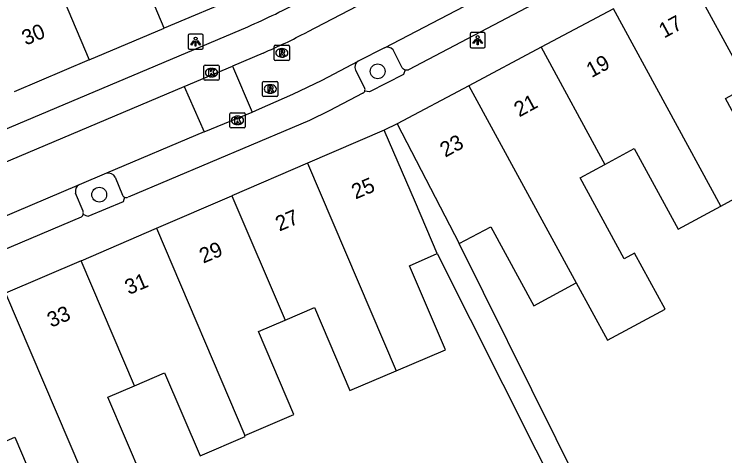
# Model space of a CAD drawing. Extents: x 159718 to 160783, y 383290 to 384030.
# Drawn here: x 160428.04 to 160474.83, y 383447.83 to 383476.93 of the extents above; entities that cross this region are included whole.
import ezdxf

# ---------------------------------------------------------------- set-up
doc = ezdxf.new("R2010")
doc.units = 0
for name, color, linetype in [('IMGEO_Boom', 7, 'Continuous'), ('IMGEO_Kolk', 7, 'Continuous'), ('IMGEO_Lichtpunt', 7, 'Continuous'), ('IMGEO_Pand', 7, 'Continuous'), ('IMGEO_Pand_nummerreeks', 7, 'Continuous'), ('IMGEO_Parkeervlak_open', 7, 'Continuous'), ('IMGEO_Rijbaan_lokaal_open', 7, 'Continuous'), ('IMGEO_Rioolput', 7, 'Continuous'), ('IMGEO_Voetpad_open', 7, 'Continuous')]:
    doc.layers.add(name, color=color, linetype=linetype)

msp = doc.modelspace()

# ---------------------------------------------------------------- linework, layer by layer
at = {"layer": 'IMGEO_Boom'}
for centre in [(160451.975, 383473.159), (160433.635, 383465.037)]:
    msp.add_circle(centre, 0.489, dxfattribs=at)
at = {"layer": 'IMGEO_Kolk'}
for p, q in [((160440.529, 383472.649), (160440.529, 383473.501)), ((160440.604, 383473.575), (160441.456, 383473.575)), ((160441.53, 383473.501), (160441.53, 383472.649)), ((160441.017, 383473.355), (160441.042, 383473.355)), ((160441.456, 383472.575), (160440.604, 383472.575)), ((160441.04, 383472.795), (160441.015, 383472.795)), ((160442.242, 383469.503), (160442.242, 383470.355)), ((160442.317, 383470.429), (160443.169, 383470.429)), ((160443.243, 383470.355), (160443.243, 383469.503)), ((160442.73, 383470.209), (160442.755, 383470.209)), ((160443.169, 383469.429), (160442.317, 383469.429)), ((160442.753, 383469.649), (160442.728, 383469.649))]:
    msp.add_line(p, q, dxfattribs=at)
for points in [[(160440.529, 383472.649), (160440.529, 383473.501)], [(160440.604, 383473.575), (160441.456, 383473.575)], [(160441.53, 383473.501), (160441.53, 383472.649)], [(160440.85, 383473.275), (160440.973, 383473.275), (160440.973, 383473.124), (160441.103, 383473.275), (160441.267, 383473.275), (160441.121, 383473.124), (160441.274, 383472.875), (160441.122, 383472.875), (160441.037, 383473.039), (160440.973, 383472.972), (160440.973, 383472.875), (160440.85, 383472.875), (160440.85, 383473.275)], [(160441.456, 383472.575), (160440.604, 383472.575)], [(160442.242, 383469.503), (160442.242, 383470.355)], [(160442.317, 383470.429), (160443.169, 383470.429)], [(160443.243, 383470.355), (160443.243, 383469.503)], [(160442.563, 383470.129), (160442.686, 383470.129), (160442.686, 383469.978), (160442.816, 383470.129), (160442.98, 383470.129), (160442.834, 383469.978), (160442.987, 383469.729), (160442.835, 383469.729), (160442.75, 383469.893), (160442.686, 383469.826), (160442.686, 383469.729), (160442.563, 383469.729), (160442.563, 383470.129)], [(160443.169, 383469.429), (160442.317, 383469.429)]]:
    msp.add_lwpolyline(points, dxfattribs=at)
for centre, start, end in [((160440.606, 383473.499), 91.552, 178.448), ((160440.606, 383473.499), 91.552, 178.448), ((160441.454, 383473.499), 1.552, 88.448), ((160441.454, 383473.499), 1.552, 88.448), ((160440.606, 383472.651), 181.552, 268.448), ((160440.606, 383472.651), 181.552, 268.448), ((160441.454, 383472.651), 271.552, 358.448), ((160441.454, 383472.651), 271.552, 358.448), ((160442.319, 383470.353), 91.552, 178.448), ((160442.319, 383470.353), 91.552, 178.448), ((160443.167, 383470.353), 1.552, 88.448), ((160443.167, 383470.353), 1.552, 88.448), ((160442.319, 383469.505), 181.552, 268.448), ((160442.319, 383469.505), 181.552, 268.448), ((160443.167, 383469.505), 271.552, 358.448), ((160443.167, 383469.505), 271.552, 358.448)]:
    msp.add_arc(centre, 0.0765, start, end, dxfattribs=at)
for centre, major_axis, ratio, start_param, end_param in [((160441.016, 383473.075), (-0.387, 0.002), 0.722429, 4.712389, 7.853982), ((160441.041, 383473.075), (-0.39, 0.002), 0.717154, 1.570796, 4.712389), ((160442.729, 383469.929), (-0.387, 0.002), 0.722429, 4.712389, 7.853982), ((160442.754, 383469.929), (-0.39, 0.002), 0.717154, 1.570796, 4.712389)]:
    msp.add_ellipse(centre, major_axis=major_axis, ratio=ratio, start_param=start_param, end_param=end_param, dxfattribs=at)
at = {"layer": 'IMGEO_Lichtpunt'}
for p, q in [((160439.483, 383475.522), (160439.483, 383474.715)), ((160439.483, 383475.522), (160439.483, 383474.715)), ((160440.385, 383475.617), (160439.577, 383475.617)), ((160440.385, 383475.617), (160439.577, 383475.617)), ((160440.479, 383474.715), (160440.479, 383475.522)), ((160440.479, 383474.715), (160440.479, 383475.522)), ((160458.058, 383475.615), (160458.058, 383474.808)), ((160458.058, 383475.615), (160458.058, 383474.808)), ((160458.96, 383475.71), (160458.152, 383475.71)), ((160458.96, 383475.71), (160458.152, 383475.71)), ((160459.054, 383474.808), (160459.054, 383475.615)), ((160459.054, 383474.808), (160459.054, 383475.615)), ((160439.577, 383474.621), (160440.385, 383474.621)), ((160439.577, 383474.621), (160440.385, 383474.621)), ((160458.152, 383474.714), (160458.96, 383474.714)), ((160458.152, 383474.714), (160458.96, 383474.714))]:
    msp.add_line(p, q, dxfattribs=at)
for points in [[(160439.857, 383475.186), (160439.896, 383475.158), (160439.708, 383474.896), (160439.67, 383474.923), (160439.857, 383475.186)], [(160439.959, 383475.138), (160440.006, 383475.138), (160440.006, 383474.816), (160439.959, 383474.816), (160439.959, 383475.138)], [(160440.069, 383475.158), (160440.107, 383475.185), (160440.294, 383474.923), (160440.255, 383474.895), (160440.069, 383475.158)], [(160458.432, 383475.279), (160458.471, 383475.251), (160458.283, 383474.989), (160458.245, 383475.016), (160458.432, 383475.279)], [(160458.534, 383475.231), (160458.581, 383475.231), (160458.581, 383474.909), (160458.534, 383474.909), (160458.534, 383475.231)], [(160458.644, 383475.251), (160458.682, 383475.278), (160458.869, 383475.016), (160458.83, 383474.988), (160458.644, 383475.251)]]:
    msp.add_lwpolyline(points, dxfattribs=at)
for centre in [(160439.982, 383475.32), (160458.557, 383475.413)]:
    msp.add_circle(centre, 0.0994, dxfattribs=at)
for centre, start, end in [((160439.577, 383475.522), 90, 180), ((160439.577, 383475.522), 90, 180), ((160440.385, 383475.522), 0, 90), ((160440.385, 383475.522), 0, 90), ((160458.152, 383475.615), 90, 180), ((160458.152, 383475.615), 90, 180), ((160458.96, 383475.615), 0, 90), ((160458.96, 383475.615), 0, 90), ((160439.577, 383474.715), 180, 270), ((160439.577, 383474.715), 180, 270), ((160440.385, 383474.715), 270, 0), ((160440.385, 383474.715), 270, 360), ((160458.152, 383474.808), 180, 270), ((160458.152, 383474.808), 180, 270), ((160458.96, 383474.808), 270, 0), ((160458.96, 383474.808), 270, 360)]:
    msp.add_arc(centre, 0.0946, start, end, dxfattribs=at)
at = {"layer": 'IMGEO_Pand'}
for points in [[(160437.922, 383476.001), (160432.152, 383489.667), (160432.064, 383489.875)], [(160429.617, 383481.871), (160432.979, 383473.909)], [(160476.413, 383472.214), (160472.268, 383479.822)], [(160442.949, 383478.128), (160437.922, 383476.001)], [(160467.502, 383477.285), (160462.733, 383474.747)], [(160474.581, 383464.288), (160467.502, 383477.285)], [(160432.979, 383473.909), (160437.922, 383476.001)], [(160462.733, 383474.747), (160457.967, 383472.21)], [(160462.733, 383474.747), (160466.94, 383467.027)], [(160432.979, 383473.909), (160428.035, 383471.817)], [(160457.967, 383472.21), (160453.253, 383469.701)], [(160457.967, 383472.21), (160465.039, 383459.226)], [(160474.581, 383464.288), (160477.78, 383466.03), (160474.869, 383471.373), (160476.413, 383472.214)], [(160452.408, 383469.29), (160447.343, 383467.106)], [(160455.891, 383461.15), (160454.461, 383464.515), (160452.408, 383469.29)], [(160453.253, 383469.701), (160457.334, 383461.812)], [(160466.94, 383467.027), (160468.871, 383468.079), (160471.77, 383462.757), (160474.581, 383464.288)], [(160447.343, 383467.106), (160442.373, 383464.964)], [(160447.343, 383467.106), (160453.18, 383453.418)], [(160465.039, 383459.226), (160467.103, 383455.437), (160470.895, 383457.501), (160468.888, 383461.187), (160468.209, 383460.817), (160465.309, 383466.139), (160466.94, 383467.027)], [(160437.405, 383462.822), (160442.373, 383464.964)], [(160442.373, 383464.964), (160445.87, 383456.765)], [(160432.435, 383460.679), (160437.405, 383462.822)], [(160437.405, 383462.822), (160443.225, 383449.175)], [(160457.334, 383461.812), (160459.434, 383462.908), (160462.264, 383457.714), (160465.039, 383459.226)], [(160453.18, 383453.418), (160456.443, 383454.809), (160454.078, 383460.356), (160455.891, 383461.15)], [(160432.435, 383460.679), (160427.467, 383458.537)], [(160435.948, 383452.441), (160432.435, 383460.679)], [(160427.467, 383458.537), (160433.298, 383444.865)], [(160445.87, 383456.765), (160447.814, 383457.594), (160450.146, 383452.125), (160453.18, 383453.418)], [(160443.225, 383449.175), (160446.457, 383450.553), (160444.125, 383456.021), (160445.87, 383456.765)], [(160435.948, 383452.441), (160437.943, 383453.292), (160440.272, 383447.829), (160443.256, 383449.102), (160443.225, 383449.175)], [(160433.765, 383445.064), (160436.521, 383446.24), (160434.195, 383451.694), (160435.948, 383452.441)], [(160423.676, 383445.899), (160426.704, 383447.19), (160426.244, 383448.268), (160428.072, 383449.047), (160430.385, 383443.623), (160430.486, 383443.666)]]:
    msp.add_lwpolyline(points, dxfattribs=at)
at = {"layer": 'IMGEO_Parkeervlak_open'}
for points in [[(160453.585, 383473.403), (160452.985, 383474.573)], [(160450.507, 383473.248), (160451.108, 383472.078)], [(160434.69, 383466.181), (160435.166, 383465.011)], [(160432.575, 383463.94), (160432.07, 383465.144)]]:
    msp.add_lwpolyline(points, dxfattribs=at)
for centre, radius, start, end in [((160452.626, 383474.301), 0.45, 37.2033, 116.1323), ((160450.932, 383473.432), 0.464, 122.1039, 203.4256), ((160453.883, 383473.626), 0.372, 216.8563, 255.3756), ((160450.88, 383471.956), 0.259, 339.3881, 28.1329), ((160434.233, 383465.945), 0.515, 27.2902, 102.7529), ((160432.575, 383465.252), 0.516, 121.3704, 192.0307), ((160435.413, 383465.111), 0.266, 201.9501, 245.5948), ((160432.242, 383463.842), 0.347, 341.9589, 16.3642)]:
    msp.add_arc(centre, radius, start, end, dxfattribs=at)
at = {"layer": 'IMGEO_Rijbaan_lokaal_open'}
for points in [[(160473.083, 383489.163), (160447.32, 383475.749)], [(160452.428, 383474.705), (160468.689, 383483.205)], [(160452.428, 383474.705), (160450.686, 383473.825)], [(160444.425, 383474.364), (160442.414, 383473.513)], [(160439.234, 383472.166), (160442.414, 383473.513)], [(160442.414, 383473.513), (160443.698, 383470.478)], [(160443.698, 383470.478), (160444.194, 383470.688), (160446.383, 383471.66), (160448.326, 383472.59), (160450.686, 383473.825)], [(160414.256, 383461.59), (160439.234, 383472.166)], [(160439.234, 383472.166), (160440.546, 383469.169)], [(160440.546, 383469.169), (160443.698, 383470.478)], [(160440.546, 383469.169), (160434.119, 383466.447)], [(160434.119, 383466.447), (160432.306, 383465.692)], [(160432.306, 383465.692), (160420.476, 383460.662)]]:
    msp.add_lwpolyline(points, dxfattribs=at)
msp.add_arc((160427.937, 383512.547), 41.591, 293.3559, 297.778, dxfattribs=at)
at = {"layer": 'IMGEO_Rioolput'}
for p, q in [((160445.16, 383473.95), (160445.16, 383474.802)), ((160445.235, 383474.876), (160446.087, 383474.876)), ((160445.648, 383474.656), (160445.673, 383474.656)), ((160446.161, 383474.802), (160446.161, 383473.95)), ((160445.671, 383474.096), (160445.646, 383474.096)), ((160446.087, 383473.876), (160445.235, 383473.876)), ((160444.397, 383471.576), (160444.397, 383472.428)), ((160444.472, 383472.502), (160445.324, 383472.502)), ((160444.885, 383472.282), (160444.91, 383472.282)), ((160445.398, 383472.428), (160445.398, 383471.576)), ((160444.908, 383471.722), (160444.883, 383471.722)), ((160445.324, 383471.502), (160444.472, 383471.502))]:
    msp.add_line(p, q, dxfattribs=at)
for points in [[(160445.16, 383473.95), (160445.16, 383474.802)], [(160445.235, 383474.876), (160446.087, 383474.876)], [(160445.749, 383474.574), (160445.497, 383474.576), (160445.497, 383474.176)], [(160445.675, 383474.495), (160445.621, 383474.495), (160445.621, 383474.414)], [(160446.161, 383474.802), (160446.161, 383473.95)], [(160445.497, 383474.176), (160445.621, 383474.176), (160445.621, 383474.338), (160445.632, 383474.338)], [(160445.621, 383474.414), (160445.673, 383474.414)], [(160445.679, 383474.309), (160445.75, 383474.176), (160445.89, 383474.176), (160445.825, 383474.302)], [(160446.087, 383473.876), (160445.235, 383473.876)], [(160444.397, 383471.576), (160444.397, 383472.428)], [(160444.472, 383472.502), (160445.324, 383472.502)], [(160444.986, 383472.2), (160444.734, 383472.202), (160444.734, 383471.802)], [(160444.912, 383472.121), (160444.858, 383472.121), (160444.858, 383472.04)], [(160445.398, 383472.428), (160445.398, 383471.576)], [(160444.734, 383471.802), (160444.858, 383471.802), (160444.858, 383471.964), (160444.869, 383471.964)], [(160444.858, 383472.04), (160444.91, 383472.04)], [(160444.916, 383471.935), (160444.987, 383471.802), (160445.127, 383471.802), (160445.062, 383471.928)], [(160445.324, 383471.502), (160444.472, 383471.502)]]:
    msp.add_lwpolyline(points, dxfattribs=at)
for centre, radius, start, end in [((160445.237, 383474.8), 0.0765, 91.552, 178.448), ((160445.237, 383474.8), 0.0765, 91.552, 178.448), ((160445.681, 383474.399), 0.0964, 77.0061, 93.1865), ((160445.695, 383474.456), 0.0378, 276.6634, 79.6772), ((160445.748, 383474.464), 0.109, 350.3612, 89.416), ((160445.746, 383474.464), 0.112, 277.5842, 350.9817), ((160446.085, 383474.8), 0.0765, 1.552, 88.448), ((160446.085, 383474.8), 0.0765, 1.552, 88.448), ((160445.631, 383474.285), 0.0533, 26.0293, 88.6989), ((160445.657, 383474.603), 0.19, 274.7715, 282.9687), ((160445.73, 383474.249), 0.108, 29.5134, 73.7905), ((160445.237, 383473.952), 0.0765, 181.552, 268.448), ((160445.237, 383473.952), 0.0765, 181.552, 268.448), ((160446.085, 383473.952), 0.0765, 271.552, 358.448), ((160446.085, 383473.952), 0.0765, 271.552, 358.448), ((160444.474, 383472.426), 0.0765, 91.552, 178.448), ((160444.474, 383472.426), 0.0765, 91.552, 178.448), ((160444.918, 383472.025), 0.0964, 77.0061, 93.1865), ((160444.932, 383472.082), 0.0378, 276.6634, 79.6772), ((160444.985, 383472.09), 0.109, 350.3612, 89.416), ((160445.322, 383472.426), 0.0765, 1.552, 88.448), ((160445.322, 383472.426), 0.0765, 1.552, 88.448), ((160444.868, 383471.911), 0.0533, 26.0293, 88.6989), ((160444.894, 383472.229), 0.19, 274.7715, 282.9687), ((160444.983, 383472.09), 0.112, 277.5842, 350.9817), ((160444.967, 383471.875), 0.108, 29.5134, 73.7905), ((160444.474, 383471.578), 0.0765, 181.552, 268.448), ((160444.474, 383471.578), 0.0765, 181.552, 268.448), ((160445.322, 383471.578), 0.0765, 271.552, 358.448), ((160445.322, 383471.578), 0.0765, 271.552, 358.448)]:
    msp.add_arc(centre, radius, start, end, dxfattribs=at)
for centre, major_axis, ratio, start_param, end_param in [((160445.647, 383474.376), (-0.387, 0.002), 0.722429, 4.712389, 7.853982), ((160445.672, 383474.376), (-0.39, 0.002), 0.717154, 1.570796, 4.712389), ((160444.884, 383472.002), (-0.387, 0.002), 0.722429, 4.712389, 7.853982), ((160444.909, 383472.002), (-0.39, 0.002), 0.717154, 1.570796, 4.712389)]:
    msp.add_ellipse(centre, major_axis=major_axis, ratio=ratio, start_param=start_param, end_param=end_param, dxfattribs=at)
at = {"layer": 'IMGEO_Voetpad_open'}
for points in [[(160468.952, 383481.115), (160467.798, 383480.536), (160454.001, 383473.268)], [(160414.146, 383463.719), (160443.414, 383476.101)], [(160453.789, 383473.266), (160453.667, 383472.943), (160451.436, 383471.805), (160451.122, 383471.865)], [(160450.997, 383471.726), (160448.781, 383470.565), (160447.487, 383469.926), (160446.34, 383469.449), (160435.53, 383464.871)], [(160453.253, 383469.701), (160452.408, 383469.29)], [(160435.303, 383464.868), (160435.203, 383464.573), (160432.884, 383463.6), (160432.572, 383463.735)], [(160432.448, 383463.559), (160421.908, 383459.097)], [(160475.937, 383439.938), (160470.105, 383436.085), (160457.334, 383461.812)], [(160455.891, 383461.15), (160468.89, 383435.282), (160468.667, 383435.135)]]:
    msp.add_lwpolyline(points, dxfattribs=at)
for centre, radius, start, end in [((160423.943, 383521.012), 48.95, 293.4389, 298.1502), ((160453.892, 383473.589), 0.339, 252.3092, 288.7718), ((160450.883, 383471.954), 0.255, 296.5563, 339.5149), ((160435.413, 383465.109), 0.265, 245.4303, 296.084), ((160432.242, 383463.836), 0.345, 306.673, 342.9941)]:
    msp.add_arc(centre, radius, start, end, dxfattribs=at)

# ---------------------------------------------------------------- texts
at = {"layer": 'IMGEO_Pand_nummerreeks'}
for s, rotation, p in [('17', 28.5791, (160470.833, 383475.316)), ('30', 22.8897, (160428.797, 383474.849)), ('19', 28.5791, (160466.056, 383472.714)), ('21', 28.5791, (160461.297, 383470.121)), ('23', 28.5791, (160456.421, 383467.465)), ('25', 22.8667, (160450.509, 383464.713)), ('27', 22.8667, (160445.499, 383462.6)), ('29', 22.8667, (160440.489, 383460.487)), ('31', 22.8667, (160435.582, 383458.418)), ('33', 22.8667, (160430.468, 383456.261))]:
    msp.add_text(s, height=1, rotation=rotation, dxfattribs=at).set_placement(p)

doc.saveas('drawing.dxf')
